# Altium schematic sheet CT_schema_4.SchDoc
size 203 x 169 mm
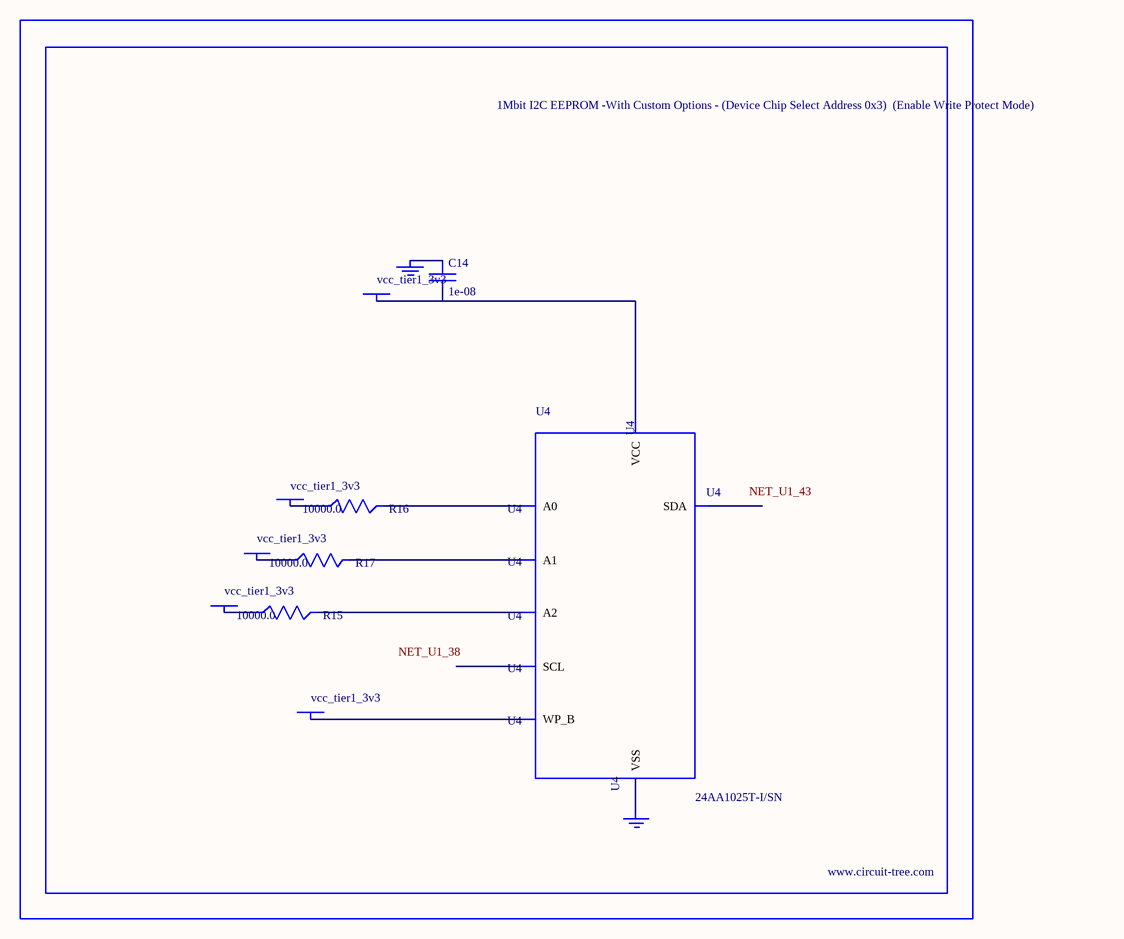
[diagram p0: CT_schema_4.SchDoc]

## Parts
BORDER3  (no value)
C14  1e-08  [C0402]
GND_INSTANCE_3_0  (no value)
GND_INSTANCE_3_1  (no value)
POWER_INSTANCE_3_0  vcc_tier1_3v3
POWER_INSTANCE_3_1  vcc_tier1_3v3
POWER_INSTANCE_3_2  vcc_tier1_3v3
POWER_INSTANCE_3_3  vcc_tier1_3v3
POWER_INSTANCE_3_4  vcc_tier1_3v3
R15  10000.0  [R0603]
R16  10000.0  [R0603]
R17  10000.0  [R0603]
U4  24AA1025T-I/SN  [SOIC-8]

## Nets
NetC14_1: C14.1 GND_INSTANCE_3_0.0(GND)
NetC14_2: C14.2 POWER_INSTANCE_3_4.0(PWR) U4.8(VCC)
NetGND_INSTANCE_3_1_0: GND_INSTANCE_3_1.0(GND) U4.4(VSS)
NetPOWER_INSTANCE_3_0_0: POWER_INSTANCE_3_0.0(PWR) R16.1
NetPOWER_INSTANCE_3_1_0: POWER_INSTANCE_3_1.0(PWR) R17.1
NetPOWER_INSTANCE_3_2_0: POWER_INSTANCE_3_2.0(PWR) R15.1
NetPOWER_INSTANCE_3_3_0: POWER_INSTANCE_3_3.0(PWR) U4.7(WP_B)
NetR15_2: R15.2 U4.3(A2)
NetR16_2: R16.2 U4.1(A0)
NetR17_2: R17.2 U4.2(A1)

Not connected (* = marked no-connect by the designer): U4 5(SDA) 6(SCL)

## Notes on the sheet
- Labels drawn without touching a wire or pin: NET_U1_38, NET_U1_43

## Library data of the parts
BORDER3 = BORDER_PAGE3
C14 = C0402C103K3RAC
GND_INSTANCE_3_0 GND_INSTANCE_3_1 = GND
POWER_INSTANCE_3_0-POWER_INSTANCE_3_4 = PWR
R15-R17 = RC0603JR-0710KL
